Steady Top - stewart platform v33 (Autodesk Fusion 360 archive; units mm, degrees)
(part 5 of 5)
sketch "Sketch2" plane through (0, 0, 0) normal (0, 0, 1) x axis (1, 0, 0)
  circle C1 centre (1.016, 5.207) radius 0.2415
  circle C2 centre (19.05, 4.699) radius 0.2415
  circle C3 centre (24.13, 11.366) radius 0.2415
  circle C4 centre (2.604, 17.462) radius 0.2415
  circle C5 centre (15.367, 16.574) radius 0.2415
  circle C6 centre (4.636, 13.97) radius 0.2415
  circle C7 centre (15.938, 14.922) radius 0.2415
  circle C8 centre (7.62, 21.209) radius 0.2415
  circle C9 centre (21.844, 9.462) radius 0.2415
  circle C10 centre (3.251, 11.155) radius 0.2415
  circle C11 centre (20.764, 16.002) radius 0.2415
  circle C12 centre (21.886, 12.785) radius 0.2415
  circle C13 centre (3.302, 9.842) radius 0.2415
  circle C14 centre (10.782, 9.144) radius 0.2415
  circle C15 centre (6.032, 7.556) radius 0.2415
  circle C16 centre (9.55, 13.931) radius 0.2415
  circle C17 centre (22.924, 16.002) radius 0.2415
  circle C18 centre (13.843, 9.652) radius 0.2415
  circle C19 centre (21.958, 13.906) radius 0.2415
  circle C20 centre (21.952, 10.922) radius 0.2415
  circle C21 centre (3.391, 15.43) radius 0.2415
  circle C22 centre (8.779, 11.267) radius 0.197
  circle C23 centre (12.256, 9.588) radius 0.197
  circle C24 centre (10.668, 7.048) radius 0.2415
  circle C25 centre (11.806, 7.43) radius 0.2415
  circle C26 centre (13.843, 7.861) radius 0.2415
  circle C27 centre (13.843, 6.414) radius 0.2415
  circle C28 centre (11.303, 5.448) radius 0.2415
  circle C29 centre (13.906, 5.207) radius 0.2415
  circle C30 centre (18.86, 8.89) radius 0.2415
  circle C31 centre (6.35, 2.54) radius 0.5
  circle C32 centre (8.89, 2.54) radius 0.5
  circle C33 centre (11.43, 2.54) radius 0.5
  circle C34 centre (13.97, 2.54) radius 0.5
  circle C35 centre (16.51, 2.54) radius 0.5
  circle C36 centre (19.05, 2.54) radius 0.5
  circle C37 centre (6.35, 20.32) radius 0.5
  circle C38 centre (8.89, 20.32) radius 0.5
  circle C39 centre (11.43, 20.32) radius 0.5
  circle C40 centre (13.97, 20.32) radius 0.5
  circle C41 centre (16.51, 20.32) radius 0.5
  circle C42 centre (19.05, 20.32) radius 0.5
  circle C43 centre (2.54, 20.32) radius 1.25
  circle C44 centre (22.86, 20.32) radius 1.25
  circle C45 centre (2.54, 2.54) radius 1.25
  circle C46 centre (22.86, 2.54) radius 1.25
create_component "CreateComponent2" sketch "Sketch1"
sketch "Sketch1" plane through (0, 0, 0) normal (0, 0, 1) x axis (1, 0, 0)
  line L1 (1.106, -0.724) -> (-1.092, -0.724)
  line L2 (1.106, 0.726) -> (1.106, -0.724)
  line L3 (-1.092, 0.726) -> (1.106, 0.726)
  line L4 (-1.092, -0.724) -> (-1.092, 0.726)
create_component "CreateComponent3" sketch "Sketch1"
sketch "Sketch1" plane through (0, 0, 0) normal (0, 0, 1) x axis (1, 0, 0)
  line L1 (1.65, -1.5) -> (-1.65, -1.5)
  line L2 (1.65, 1.5) -> (1.65, -1.5)
  line L3 (-1.65, 1.5) -> (1.65, 1.5)
  line L4 (-1.65, -1.5) -> (-1.65, 1.5)
create_component "CreateComponent4" sketch "Sketch1"
sketch "Sketch1" plane through (0, 0, 0) normal (0, 0, 1) x axis (1, 0, 0)
  line L1 (0.83, -0.47) -> (-0.838, -0.47)
  line L2 (0.83, 0.48) -> (0.83, -0.47)
  line L3 (-0.838, 0.48) -> (0.83, 0.48)
  line L4 (-0.838, -0.47) -> (-0.838, 0.48)
create_component "CreateComponent5" sketch "Sketch1"
sketch "Sketch1" plane through (0, 0, 0) normal (0, 0, 1) x axis (1, 0, 0)
  line L1 (1.9, -1.4) -> (-1.9, -1.4)
  line L2 (1.9, 1.4) -> (1.9, -1.4)
  line L3 (-1.9, 1.4) -> (1.9, 1.4)
  line L4 (-1.9, -1.4) -> (-1.9, 1.4)
create_component "CreateComponent6" sketch "Sketch1"
sketch "Sketch1" plane through (0, 0, 0) normal (0, 0, 1) x axis (1, 0, 0)
  line L1 (1.1, -1.05) -> (-1.6, -1.05)
  line L2 (1.1, 1.05) -> (1.1, -1.05)
  line L3 (-1.6, 1.05) -> (1.1, 1.05)
  line L4 (-1.6, -1.05) -> (-1.6, 1.05)
create_component "CreateComponent7" sketch "Sketch1"
sketch "Sketch1" plane through (0, 0, 0) normal (0, 0, 1) x axis (1, 0, 0)
  line L1 (6.85, -0.635) -> (-7.62, -0.635)
  line L2 (6.85, 0.635) -> (6.85, -0.635)
  line L3 (-7.62, 0.635) -> (6.85, 0.635)
  line L4 (-7.62, -0.635) -> (-7.62, 0.635)
create_component "CreateComponent8" sketch "Sketch1"
sketch "Sketch1" plane through (0, 0, 0) normal (0, 0, 1) x axis (1, 0, 0)
  line L1 (2, -2) -> (-2, -2)
  line L2 (2, 2) -> (2, -2)
  line L3 (-2, 2) -> (2, 2)
  line L4 (-2, -2) -> (-2, 2)
create_component "CreateComponent9" sketch "Sketch1"
sketch "Sketch1" plane through (0, 0, 0) normal (0, 0, 1) x axis (1, 0, 0)
  line L1 (3.1, -2.086) -> (-3, -2.086)
  line L2 (3.1, 2.214) -> (3.1, -2.086)
  line L3 (-3, 2.214) -> (3.1, 2.214)
  line L4 (-3, -2.086) -> (-3, 2.214)
create_component "CreateComponent10" sketch "Sketch1"
sketch "Sketch1" plane through (0, 0, 0) normal (0, 0, 1) x axis (1, 0, 0)
  line L1 (0.75, -0.75) -> (-0.75, -0.75)
  line L2 (0.75, 0.75) -> (0.75, -0.75)
  line L3 (-0.75, 0.75) -> (0.75, 0.75)
  line L4 (-0.75, -0.75) -> (-0.75, 0.75)
create_component "CreateComponent11" sketch "Sketch1"
sketch "Sketch1" plane through (0, 0, 0) normal (0, 0, 1) x axis (1, 0, 0)
  line L1 (0.898, -0.898) -> (-0.898, -0.898)
  line L2 (0.898, 0.898) -> (0.898, -0.898)
  line L3 (-0.898, 0.898) -> (0.898, 0.898)
  line L4 (-0.898, -0.898) -> (-0.898, 0.898)
create_component "CreateComponent12" sketch "Sketch1"
sketch "Sketch1" plane through (0, 0, 0) normal (0, 0, 1) x axis (1, 0, 0)
  line L1 (9.248, -0.011) -> (-0.013, -0.011)
  line L2 (9.248, 2.644) -> (9.248, -0.011)
  line L3 (-0.013, 2.644) -> (9.248, 2.644)
  line L4 (-0.013, -0.011) -> (-0.013, 2.644)
create_component "CreateComponent13" sketch "Sketch1"
sketch "Sketch1" plane through (0, 0, 0) normal (0, 0, 1) x axis (1, 0, 0)
  line L1 (0.45, -1.1) -> (-0.45, -1.1)
  line L2 (0.45, 1.1272) -> (0.45, -1.1)
  line L3 (-0.45, 1.1272) -> (0.45, 1.1272)
  line L4 (-0.45, -1.1) -> (-0.45, 1.1272)
create_component "CreateComponent14" sketch "Sketch1"
sketch "Sketch1" plane through (0, 0, 0) normal (0, 0, 1) x axis (1, 0, 0)
  line L1 (2.7, -2) -> (-3.524, -2)
  line L2 (2.7, 2) -> (2.7, -2)
  line L3 (-3.524, 2) -> (2.7, 2)
  line L4 (-3.524, -2) -> (-3.524, 2)
create_component "CreateComponent15" sketch "Sketch1"
sketch "Sketch1" plane through (0, 0, 0) normal (0, 0, 1) x axis (1, 0, 0)
  line L1 (1.6, -0.7) -> (-1.6, -0.7)
  line L2 (1.6, 0.7) -> (1.6, -0.7)
  line L3 (-1.6, 0.7) -> (1.6, 0.7)
  line L4 (-1.6, -0.7) -> (-1.6, 0.7)
create_component "CreateComponent16" sketch "Sketch1"
sketch "Sketch1" plane through (0, 0, 0) normal (0, 0, 1) x axis (1, 0, 0)
  line L1 (1.651, -1.016) -> (-1.651, -1.016)
  line L2 (1.651, 1.016) -> (1.651, -1.016)
  line L3 (-1.651, 1.016) -> (1.651, 1.016)
  line L4 (-1.651, -1.016) -> (-1.651, 1.016)
create_component "CreateComponent17" sketch "Sketch1"
sketch "Sketch1" plane through (0, 0, 0) normal (0, 0, 1) x axis (1, 0, 0)
  line L1 (2.515, -3.121) -> (-2.515, -3.121)
  line L2 (2.515, 3.121) -> (2.515, -3.121)
  line L3 (-2.515, 3.121) -> (2.515, 3.121)
  line L4 (-2.515, -3.121) -> (-2.515, 3.121)
create_component "CreateComponent18" sketch "Sketch1"
sketch "Sketch1" plane through (0, 0, 0) normal (0, 0, 1) x axis (1, 0, 0)
  line L1 (3.794, 0.016) -> (0.016, 0.016)
  line L2 (3.794, 3.794) -> (3.794, 0.016)
  line L3 (0.016, 3.794) -> (3.794, 3.794)
  line L4 (0.016, 0.016) -> (0.016, 3.794)
as_built_joint "As-built1"
named bodies: "Board", "0805-NO", "SOT23-5", "0603-NO", "RESPACK_4X0603", "SOT363", "1X06_ROUND_70", "MOUNTINGHOLE_2.5_PLATED", "JST_SH4", "FIDUCIAL_1MM", "PCBFEAT-REV-040", "STEMMAQT", "CHIPLED_0603_NOOUTLINE", "BNO080", "XTAL3215", "SOLDERJUMPER_ARROW_NOPASTE", "TSSOP16", "ADAFRUIT_3.5MM"

design "PCB1"
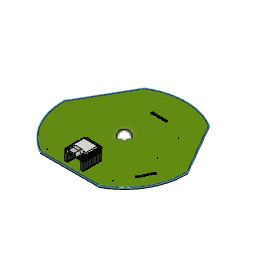
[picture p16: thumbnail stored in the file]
derived_context "DerivedContext1"
derived_context "DerivedContext2"
sketch "Outline" plane through (0, 0, 57.7) normal (0, 0, -1) x axis (1, 0, 0)
  line L1 (-30.9165, -50.2511) -> (-58.977, -1.6489)
  line L2 (58.977, -1.6489) -> (30.9165, -50.2511)
  line L3 (-28.0605, 51.9) -> (28.0605, 51.9)
  arc A1 centre (0, 0) radius 59 clockwise from (30.9165, -50.2511) to (-30.9165, -50.2511)
  arc A2 centre (0, 0) radius 59 clockwise from (28.0605, 51.9) to (58.977, -1.6489)
  arc A3 centre (0, 0) radius 59 clockwise from (-58.977, -1.6489) to (-28.0605, 51.9)
step sketch "Outline"
canvas "Canvas1"
canvas "Canvas2"
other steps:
base_feature "Base Feature1"
base_feature "Base Feature1"
base_feature "Base Feature1"
base_feature "Base Feature1"
base_feature "Base Feature1"
base_feature "Base Feature1"
base_feature "Base Feature1"
base_feature "Base Feature1"
base_feature "Base Feature1"
base_feature "Base Feature1"
base_feature "Base Feature1"
base_feature "Base Feature1"
base_feature "Base Feature1"
base_feature "Base Feature1"
base_feature "Base Feature1"
base_feature "Base Feature1"
base_feature "Base Feature1"
base_feature "Base Feature1"
base_feature "Base Feature1"
base_feature "Base Feature1"
base_feature "Base Feature1"
base_feature "Base Feature1"
base_feature "Base Feature1"
base_feature "Base Feature1"
base_feature "Base Feature1"
base_feature "Base Feature1"
base_feature "Base Feature1"
base_feature "Base Feature1"
base_feature "Base Feature1"
base_feature "Base Feature1"
base_feature "Base Feature1"
base_feature "Base Feature1"
base_feature "Base Feature1"
base_feature "Base Feature1"
base_feature "Base Feature1"
base_feature "Base Feature1"
base_feature "Base Feature1"
base_feature "Base Feature1"
base_feature "Base Feature1"
base_feature "Base Feature1"
base_feature "Base Feature1"
base_feature "Base Feature1"
base_feature "Base Feature1"
derived_base_feature "Derived Base Feature"
box_primitive "BoxPrimitive1" DistanceX 16.875 DistanceY 11.279 DistanceZ 0.1 OffsetDistanceX 0 OffsetDistanceY 0
box_primitive "BoxPrimitive1" DistanceX 8.89 DistanceY 6.248 DistanceZ 0.1 OffsetDistanceX 0 OffsetDistanceY 0
box_primitive "BoxPrimitive1" DistanceX 4.997 DistanceY 2.017 DistanceZ 0.1 OffsetDistanceX 0 OffsetDistanceY 0
box_primitive "BoxPrimitive1" DistanceX 4.997 DistanceY 2.017 DistanceZ 0.1 OffsetDistanceX 0 OffsetDistanceY 0
base_feature "Base Feature1"
base_feature "Base Feature1"
base_feature "Base Feature1"
base_feature "Base Feature1"
base_feature "Base Feature1"
base_feature "Base Feature1"
base_feature "Base Feature1"
base_feature "Base Feature1"
base_feature "Base Feature1"
base_feature "Base Feature1"
base_feature "Base Feature1"
base_feature "Base Feature1"
base_feature "Base Feature1"
base_feature "Base Feature1"
base_feature "Base Feature1"
base_feature "Base Feature1"
base_feature "Base Feature1"
base_feature "Base Feature1"
base_feature "Base Feature1"
base_feature "Base Feature1"
base_feature "Base Feature1"
base_feature "Base Feature1"
base_feature "Base Feature1"
base_feature "Base Feature1"
base_feature "Base Feature1"
base_feature "Base Feature1"
base_feature "Base Feature1"
base_feature "Base Feature1"
base_feature "Base Feature1"
base_feature "Base Feature1"
base_feature "Base Feature1"
base_feature "Base Feature1"
base_feature "Base Feature1"
base_feature "Base Feature1"
base_feature "Base Feature1"
base_feature "Base Feature1"
base_feature "Base Feature1"
base_feature "Base Feature1"
base_feature "Base Feature1"
base_feature "Base Feature1"
base_feature "Base Feature1"
base_feature "Base Feature1"
base_feature "Base Feature1"
base_feature "Base Feature1"
base_feature "Base Feature1"
base_feature "Base Feature1"
base_feature "Base Feature1"
base_feature "Base Feature1"
base_feature "Base Feature1"
base_feature "Base Feature1"
base_feature "Base Feature1"
base_feature "Base Feature1"
base_feature "Base Feature1"
base_feature "Base Feature1"
base_feature "Base Feature1"
base_feature "Base Feature1"
base_feature "Base Feature1"
base_feature "Base Feature1"
base_feature "Base Feature1"
base_feature "Base Feature1"
base_feature "Base Feature1"
pcbextrude "PCBExtrude1"
pcbextrude "PCBExtrude1"
pcbextrude "PCBExtrude1"
pcbextrude "PCBExtrude1"
extrude "Extrude1" new body sketch "Outline" blind 1.5
pcbextrude "PCBExtrude1"
pcbextrude "PCBExtrude2" bodies "CopperHoles"
create_component "CreateComponent1"
create_component "CreateComponent2"
create_component "CreateComponent3"
create_component "CreateComponent4"
create_component "CreateComponent5"
create_component "CreateComponent6"
as_built_joint "As-built1"
create_component "CreateComponent1"
create_component "CreateComponent2"
create_component "CreateComponent3"
create_component "CreateComponent4"
create_component "CreateComponent5"
create_component "CreateComponent1"
create_component "CreateComponent1"
create_component "CreateComponent1"
create_component "CreateComponent2"
create_component "CreateComponent3"
create_component "CreateComponent4"
create_component "CreateComponent1"
create_component "CreateComponent2"
create_component "CreateComponent3"
create_component "CreateComponent4"
create_component "CreateComponent1"
create_component "CreateComponent2"
create_component "CreateComponent3"
create_component "CreateComponent4"
create_component "CreateComponent5"
create_component "CreateComponent6"
create_component "CreateComponent7"
create_component "CreateComponent8"
create_component "CreateComponent9"
create_component "CreateComponent10"
create_component "CreateComponent11"
create_component "CreateComponent12"
create_component "CreateComponent13"
create_component "CreateComponent2"
create_component "CreateComponent1"
create_component "CreateComponent1"
create_component "CreateComponent2"
create_component "CreateComponent2"
create_component "CreateComponent1"
create_component "CreateComponent2"
create_component "CreateComponent3"
create_component "CreateComponent1"
create_component "CreateComponent2"
create_component "CreateComponent3"
create_component "CreateComponent1"
create_component "CreateComponent1"
create_component "CreateComponent2"
create_component "CreateComponent2"
create_component "CreateComponent1"
create_component "CreateComponent2"
create_component "CreateComponent3"
create_component "CreateComponent1"
create_component "CreateComponent2"
create_component "CreateComponent4"
create_component "CreateComponent1"
create_component "CreateComponent2"
create_component "CreateComponent4"
create_component "CreateComponent1"
create_component "CreateComponent1"
create_component "CreateComponent2"
create_component "CreateComponent2"
create_component "CreateComponent1"
create_component "CreateComponent2"
create_component "CreateComponent3"
create_component "CreateComponent1"
create_component "CreateComponent2"
create_component "CreateComponent5"
create_component "CreateComponent1"
create_component "CreateComponent1"
create_component "CreateComponent2"
create_component "CreateComponent2"
create_component "CreateComponent1"
create_component "CreateComponent2"
create_component "CreateComponent3"
create_component "CreateComponent1"
create_component "CreateComponent2"
create_component "CreateComponent4"
create_component "CreateComponent1"
create_component "CreateComponent2"
create_component "CreateComponent6"
create_component "CreateComponent1"
create_component "CreateComponent1"
create_component "CreateComponent1"
create_component "CreateComponent2"
create_component "CreateComponent1"
create_component "CreateComponent3"
create_component "CreateComponent1"
create_component "CreateComponent2"
create_component "CreateComponent1"
create_component "CreateComponent1"
create_component "CreateComponent2"
create_component "CreateComponent1"
create_component "CreateComponent3"
create_component "CreateComponent1"
create_component "CreateComponent4"
create_component "CreateComponent1"
create_component "CreateComponent7"
create_component "CreateComponent1"
create_component "CreateComponent1"
create_component "CreateComponent1"
create_component "CreateComponent2"
create_component "CreateComponent1"
create_component "CreateComponent3"
create_component "CreateComponent1"
create_component "CreateComponent2"
create_component "CreateComponent1"
create_component "CreateComponent1"
create_component "CreateComponent2"
create_component "CreateComponent1"
create_component "CreateComponent3"
create_component "CreateComponent1"
create_component "CreateComponent4"
create_component "CreateComponent1"
named bodies: "CopperHoles"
